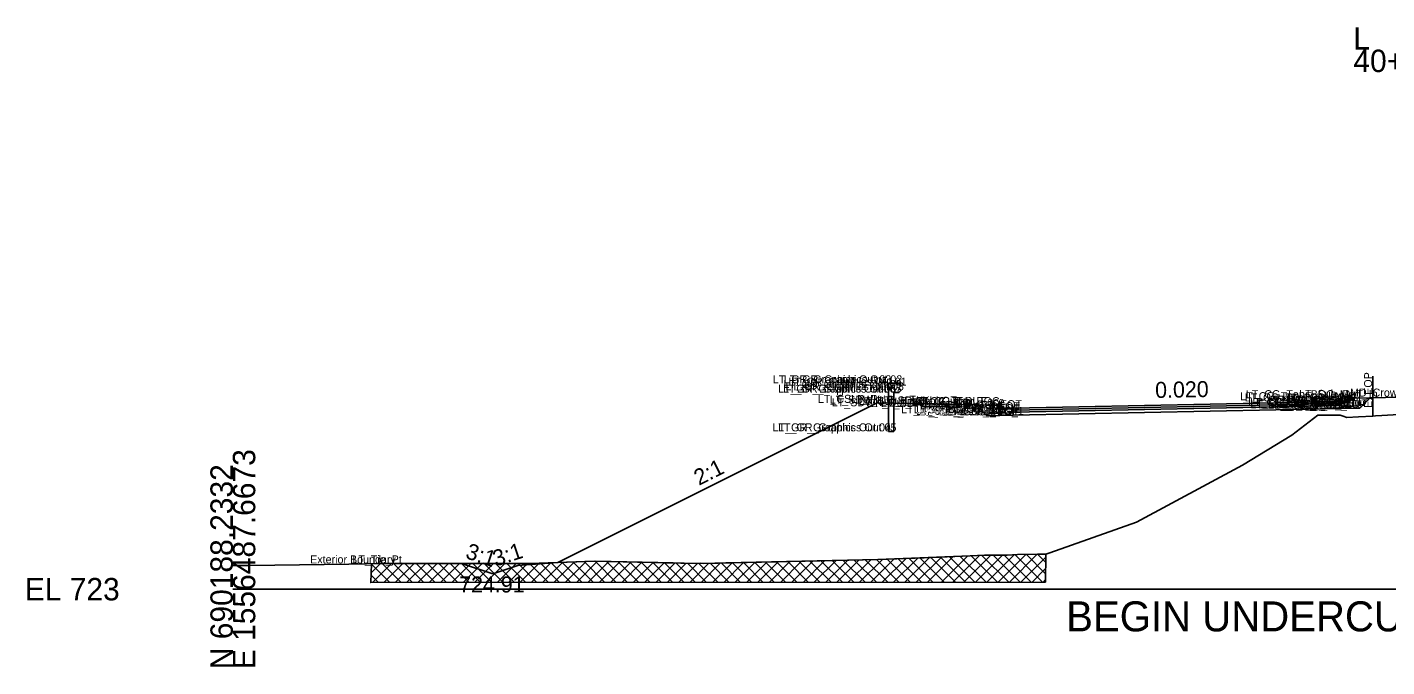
# Model space of a CAD drawing. Extents: x -26 to 6300, y -10 to 9577.
# Drawn here: x -25.7 to 144.2, y 6490.3 to 6570.2 of the extents above; entities that cross this region are included whole.
import ezdxf

# ---------------------------------------------------------------- set-up
doc = ezdxf.new("R2010")
doc.units = 0
for name, color, linetype in [('Default', 7, 'Continuous'), ('Exist Cross Section Cell', 7, 'Continuous'), ('Exist XS Ground Line', 7, 'Continuous'), ('Prop CMT Conc Surface', 7, 'Continuous'), ('Prop CMT Concrete Structures', 7, 'Continuous'), ('Prop CMT Guardrail Graphics', 7, 'Continuous'), ('Prop CMT Pvmt Course 1', 7, 'Continuous'), ('Prop CMT Pvmt Course 1 CG', 7, 'Continuous'), ('Prop CMT Pvmt Course 2', 7, 'Continuous'), ('Prop CMT Pvmt Course 3', 7, 'Continuous'), ('Prop CMT Pvmt Surface', 7, 'Continuous'), ('Prop CMT Slope Grass', 7, 'Continuous'), ('Prop CMT Subgrade Earthwork', 7, 'Continuous'), ('Prop XS DDE', 7, 'Continuous'), ('Prop XS DDE Text', 7, 'Continuous'), ('Prop XS Label Text', 7, 'Continuous'), ('Prop XS SE Text', 7, 'Continuous'), ('Prop XS Side Slope Text', 7, 'Continuous'), ('Prop XS Undercut Exc', 7, 'Continuous'), ('Prop XS Undercut Exc Hatch', 7, 'Continuous'), ('Prop XSC Text', 7, 'Continuous')]:
    doc.layers.add(name, color=color, linetype=linetype)

msp = doc.modelspace()

# ---------------------------------------------------------------- linework, layer by layer
at = {"layer": 'Exist Cross Section Cell'}
msp.add_line((0, 6500), (150, 6500), dxfattribs=at)
at = {"layer": 'Exist XS Ground Line'}
msp.add_lwpolyline([(0, 6502.94), (2.15, 6502.97), (14.48, 6503.13), (21.06, 6503.23), (37.12, 6503.19), (45.16, 6503.49), (57.75, 6503.22), (58.42, 6503.23), (58.81, 6503.22), (80.6, 6503.7), (92.13, 6504.15), (93.92, 6504.24), (96.73, 6504.24), (98.03, 6504.32), (100.53, 6504.36), (101.56, 6504.36), (102.06, 6504.54), (112.9, 6508.35), (126.16, 6515.5), (132.33, 6519.23), (135.58, 6521.72), (138.34, 6521.72), (138.74, 6521.59), (139.17, 6521.45), (140.65, 6521.54), (142.44, 6521.62), (142.77, 6521.66), (143.57, 6521.71), (149.23, 6522.02)], dxfattribs=at)
at = {"layer": 'Prop CMT Conc Surface'}
for points in [[(91, 6523.07), (86, 6523.17)], [(138.5, 6523.42), (139.25, 6523.44), (139.25, 6523.6), (140.01, 6523.85)], [(95.5, 6522.48), (95.5, 6522.98), (95, 6522.98)], [(97.5, 6522.6), (95.5, 6522.48)]]:
    msp.add_lwpolyline(points, dxfattribs=at)
at = {"layer": 'Prop CMT Concrete Structures'}
for points in [[(86, 6522.84), (86, 6523.17)], [(86, 6523.17), (91, 6523.07)], [(91, 6523.07), (91, 6522.74)], [(138.5, 6523.42), (139.25, 6523.44), (139.25, 6523.6), (140.01, 6523.85)], [(138.5, 6522.84), (138.5, 6523.42)], [(140.01, 6523.85), (140.01, 6522.87)], [(91, 6522.74), (86, 6522.84)], [(97.5, 6522.6), (95.5, 6522.48), (95.5, 6522.98), (95, 6522.98)], [(95, 6522.98), (95, 6521.97), (97.5, 6522.02)], [(97.5, 6522.02), (97.5, 6522.6)], [(140.01, 6522.87), (138.5, 6522.84)]]:
    msp.add_lwpolyline(points, dxfattribs=at)
at = {"layer": 'Prop CMT Guardrail Graphics'}
for points in [[(81.9, 6519.71), (81.9, 6525.71)], [(81.9, 6525.71), (83.23, 6525.71), (83.51, 6525.42)], [(83.51, 6524.84), (83.23, 6524.55), (82.57, 6524.55)], [(83.51, 6525.42), (83.23, 6525.13)], [(83.23, 6525.13), (83.51, 6524.84)], [(82.57, 6524.55), (82.57, 6519.71)], [(82.57, 6519.71), (81.9, 6519.71)]]:
    msp.add_lwpolyline(points, dxfattribs=at)
at = {"layer": 'Prop CMT Pvmt Course 1'}
for points in [[(138.5, 6523.42), (97.5, 6522.6)], [(97.5, 6522.35), (138.5, 6523.17)], [(138.5, 6523.17), (138.5, 6523.42)], [(138.5, 6523.17), (138.5, 6523.17), (138.5, 6523.17)], [(97.5, 6522.6), (97.5, 6522.35)]]:
    msp.add_lwpolyline(points, dxfattribs=at)
at = {"layer": 'Prop CMT Pvmt Course 1 CG'}
for points in [[(97.5, 6522.02), (94.5, 6521.96), (94.2, 6521.66)], [(94.2, 6521.66), (97.5, 6521.73)], [(97.5, 6521.77), (97.5, 6522.02)], [(138.5, 6522.84), (140.51, 6522.88), (140.8, 6522.59)], [(138.5, 6522.59), (138.5, 6522.84)], [(140.76, 6522.59), (138.5, 6522.55)]]:
    msp.add_lwpolyline(points, dxfattribs=at)
at = {"layer": 'Prop CMT Pvmt Course 2'}
for points in [[(138.5, 6523.17), (97.5, 6522.35)], [(138.5, 6522.92), (138.5, 6523.17)], [(97.5, 6522.1), (138.5, 6522.92)], [(97.5, 6522.35), (97.5, 6522.1)]]:
    msp.add_lwpolyline(points, dxfattribs=at)
at = {"layer": 'Prop CMT Pvmt Course 3'}
for points in [[(138.5, 6522.92), (97.5, 6522.1)], [(97.5, 6521.73), (138.5, 6522.55)], [(97.5, 6522.1), (97.5, 6521.73)], [(138.5, 6522.55), (138.5, 6522.92)]]:
    msp.add_lwpolyline(points, dxfattribs=at)
at = {"layer": 'Prop CMT Pvmt Surface'}
msp.add_lwpolyline([(138.5, 6523.42), (97.5, 6522.6)], dxfattribs=at)
at = {"layer": 'Prop CMT Slope Grass'}
msp.add_line((80.5, 6523.27), (40.59, 6503.32), dxfattribs=at)
for points in [[(95, 6522.98), (80.5, 6523.27)], [(140.01, 6523.85), (150, 6524.05)]]:
    msp.add_lwpolyline(points, dxfattribs=at)
at = {"layer": 'Prop CMT Subgrade Earthwork'}
msp.add_line((94.2, 6521.66), (92.84, 6523.02), dxfattribs=at)
for points in [[(142.1, 6523.89), (140.8, 6522.59)], [(97.5, 6521.73), (94.2, 6521.66)], [(138.5, 6522.55), (97.5, 6521.73)], [(140.8, 6522.59), (138.5, 6522.55)], [(138.5, 6522.55), (138.5, 6522.55)]]:
    msp.add_lwpolyline(points, dxfattribs=at)
at = {"layer": 'Prop XS DDE'}
for p, q in [((35.61, 6502.95), (32.48, 6501.91)), ((40.59, 6503.32), (35.61, 6502.95))]:
    msp.add_line(p, q, dxfattribs=at)
msp.add_lwpolyline([(32.48, 6501.91), (28.58, 6503.21)], dxfattribs=at)
at = {"layer": 'Prop XS Label Text'}
msp.add_line((142.44, 6526.62), (142.44, 6521.62), dxfattribs=at)
at = {"layer": 'Prop XS Undercut Exc'}
for p, q in [((100.53, 6504.36), (98.03, 6504.32)), ((101.56, 6504.36), (100.53, 6504.36)), ((101.55, 6500.89), (101.56, 6504.36)), ((25.95, 6500.83), (28.34, 6503.21)), ((84.11, 6503.83), (84.11, 6503.83)), ((86.36, 6503.92), (84.12, 6503.83)), ((92.13, 6504.15), (86.36, 6503.92)), ((93.92, 6504.24), (92.13, 6504.15)), ((95.32, 6504.24), (93.92, 6504.24)), ((96.73, 6504.24), (95.32, 6504.24)), ((98.03, 6504.32), (96.73, 6504.24)), ((101.27, 6500.89), (101.55, 6501.17))]:
    msp.add_line(p, q, dxfattribs=at)
for points in [[(25.03, 6503.22), (17.32, 6503.17), (17.23, 6500.82), (101.55, 6500.87)], [(40.59, 6503.32), (37.12, 6503.19), (25.03, 6503.22)], [(55.01, 6503.28), (45.34, 6503.49), (40.59, 6503.32)], [(84.12, 6503.83), (80.6, 6503.7), (61.6, 6503.28), (58.81, 6503.22), (58.42, 6503.23), (57.75, 6503.22), (55.01, 6503.28)]]:
    msp.add_lwpolyline(points, dxfattribs=at)
at = {"layer": 'Prop XS Undercut Exc Hatch'}
for p, q in [((95.6, 6500.88), (99.06, 6504.34)), ((97.02, 6500.88), (100.5, 6504.36)), ((99.14, 6504.34), (101.55, 6501.92)), ((100.53, 6504.36), (101.56, 6503.33)), ((17.28, 6502.05), (18.4, 6503.18)), ((17.32, 6503.13), (19.63, 6500.82)), ((17.46, 6500.82), (19.83, 6503.19)), ((18.69, 6503.18), (21.04, 6500.82)), ((18.88, 6500.82), (21.25, 6503.2)), ((20.09, 6503.19), (22.46, 6500.82)), ((20.29, 6500.82), (22.67, 6503.2)), ((21.5, 6503.2), (23.87, 6500.83)), ((21.71, 6500.82), (24.1, 6503.21)), ((22.9, 6503.21), (25.28, 6500.83)), ((23.12, 6500.82), (25.52, 6503.22)), ((24.31, 6503.21), (26.7, 6500.83)), ((24.54, 6500.83), (26.93, 6503.21)), ((25.72, 6503.22), (28.11, 6500.83)), ((27.14, 6503.21), (29.52, 6500.83)), ((27.37, 6500.83), (29.75, 6503.21)), ((28.56, 6503.21), (30.94, 6500.83)), ((28.78, 6500.83), (31.16, 6503.2)), ((29.97, 6503.21), (32.35, 6500.83)), ((30.2, 6500.83), (32.57, 6503.2)), ((31.39, 6503.2), (33.76, 6500.83)), ((31.61, 6500.83), (33.98, 6503.2)), ((32.81, 6503.2), (35.18, 6500.83)), ((33.03, 6500.83), (35.39, 6503.19)), ((34.23, 6503.19), (36.59, 6500.83)), ((34.44, 6500.83), (36.8, 6503.19)), ((35.65, 6503.19), (38, 6500.83)), ((35.86, 6500.83), (38.26, 6503.23)), ((37.06, 6503.19), (39.42, 6500.83)), ((37.27, 6500.83), (39.73, 6503.29)), ((38.43, 6503.24), (40.83, 6500.84)), ((38.69, 6500.83), (41.19, 6503.34)), ((39.79, 6503.29), (42.24, 6500.84)), ((40.1, 6500.84), (42.66, 6503.39)), ((41.16, 6503.34), (43.66, 6500.84)), ((41.52, 6500.84), (44.13, 6503.44)), ((42.52, 6503.39), (45.07, 6500.84)), ((42.93, 6500.84), (45.58, 6503.48)), ((43.89, 6503.44), (46.48, 6500.84)), ((44.35, 6500.84), (46.96, 6503.45)), ((45.25, 6503.48), (47.9, 6500.84)), ((45.76, 6500.84), (48.35, 6503.42)), ((46.69, 6503.46), (49.31, 6500.84)), ((47.18, 6500.84), (49.73, 6503.39)), ((48.14, 6503.43), (50.72, 6500.84)), ((48.59, 6500.84), (51.12, 6503.36)), ((49.58, 6503.4), (52.14, 6500.84)), ((50.01, 6500.84), (52.5, 6503.33)), ((51.03, 6503.36), (53.55, 6500.84)), ((51.42, 6500.84), (53.89, 6503.3)), ((52.47, 6503.33), (54.96, 6500.84)), ((52.84, 6500.84), (55.27, 6503.27)), ((53.92, 6503.3), (56.38, 6500.85)), ((54.25, 6500.84), (56.65, 6503.24)), ((55.36, 6503.27), (57.79, 6500.85)), ((55.67, 6500.84), (58.05, 6503.22)), ((56.81, 6503.24), (59.2, 6500.85)), ((57.08, 6500.85), (59.47, 6503.24)), ((58.24, 6503.22), (60.62, 6500.85)), ((58.5, 6500.85), (60.92, 6503.27)), ((59.64, 6503.24), (62.03, 6500.85)), ((59.91, 6500.85), (62.37, 6503.3)), ((61.02, 6503.27), (63.44, 6500.85)), ((61.33, 6500.85), (63.81, 6503.33)), ((62.41, 6503.3), (64.86, 6500.85)), ((62.74, 6500.85), (65.26, 6503.36)), ((63.79, 6503.33), (66.27, 6500.85)), ((64.16, 6500.85), (66.7, 6503.39)), ((65.18, 6503.36), (67.68, 6500.85)), ((65.57, 6500.85), (68.15, 6503.42)), ((66.56, 6503.39), (69.1, 6500.85)), ((66.99, 6500.85), (69.59, 6503.46)), ((67.94, 6503.42), (70.51, 6500.85)), ((68.41, 6500.85), (71.04, 6503.49)), ((69.33, 6503.45), (71.92, 6500.85)), ((69.82, 6500.85), (72.49, 6503.52)), ((70.71, 6503.48), (73.34, 6500.86)), ((71.24, 6500.85), (73.93, 6503.55)), ((72.1, 6503.51), (74.75, 6500.86)), ((72.65, 6500.86), (75.38, 6503.58)), ((73.48, 6503.54), (76.16, 6500.86)), ((74.07, 6500.86), (76.82, 6503.61)), ((74.86, 6503.57), (77.58, 6500.86)), ((75.48, 6500.86), (78.27, 6503.65)), ((76.25, 6503.6), (78.99, 6500.86)), ((76.9, 6500.86), (79.71, 6503.68)), ((77.63, 6503.63), (80.4, 6500.86)), ((78.31, 6500.86), (81.17, 6503.72)), ((79.02, 6503.66), (81.82, 6500.86)), ((79.73, 6500.86), (82.64, 6503.78)), ((80.4, 6503.69), (83.23, 6500.86)), ((81.14, 6500.86), (84.11, 6503.83)), ((81.76, 6503.74), (84.64, 6500.86)), ((82.56, 6500.86), (85.59, 6503.89)), ((83.12, 6503.8), (86.06, 6500.86)), ((83.97, 6500.86), (87.06, 6503.95)), ((84.49, 6503.85), (87.47, 6500.86)), ((85.39, 6500.86), (88.53, 6504.01)), ((85.85, 6503.9), (88.88, 6500.87)), ((86.8, 6500.86), (90, 6504.07)), ((87.21, 6503.96), (90.3, 6500.87)), ((88.41, 6504), (91.54, 6500.87)), ((88.52, 6500.86), (91.79, 6504.14)), ((89.53, 6504.05), (92.71, 6500.87)), ((89.94, 6500.87), (93.28, 6504.21)), ((90.89, 6504.1), (94.12, 6500.87)), ((91.35, 6500.87), (94.72, 6504.24)), ((92.25, 6504.15), (95.53, 6500.88)), ((92.77, 6500.87), (96.11, 6504.21)), ((93.59, 6504.22), (96.94, 6500.88)), ((94.19, 6500.87), (97.56, 6504.25)), ((94.99, 6504.24), (98.35, 6500.88)), ((96.43, 6504.22), (99.76, 6500.89)), ((97.8, 6504.26), (101.17, 6500.89)), ((98.44, 6500.88), (101.56, 6504)), ((17.27, 6501.77), (18.22, 6500.82)), ((99.86, 6500.89), (101.55, 6502.58))]:
    msp.add_line(p, q, dxfattribs=at)

# ---------------------------------------------------------------- texts
at = {"layer": 'Default'}
for s, height, p in [('LT_GR_Graphics Out 03', 1, (67.47, 6525.71)), ('LT_GR_Graphics Out 02', 1, (68.84, 6525.71)), ('LT_GR_Graphics Out 01', 1, (69.4, 6525.42)), ('LT_GR_Graphics Out 06', 1, (68.11, 6524.55)), ('LT_GR_Graphics Out 07', 1, (68.75, 6524.55)), ('LT_GR_Graphics Out 09', 1, (68.78, 6525.13)), ('LT_GR_Graphics Out 08', 1, (69.05, 6524.84)), ('LT_CG_Top_BOC_Med', 1, (126.57, 6523.85)), ('LT_Sub_DLT_In', 1, (133.22, 6523.89)), ('MD_Crown Point', 1, (139.58, 6524.05)), ('LT_CSLP_Pnt', 1, (73.1, 6523.27)), ('LT_SDWK_Out_Top', 1, (74.58, 6523.17)), ('LT_SDWK_Out_Bot', 1, (74.83, 6522.84)), ('LT_Sub_Trench_Out_DLT', 1, (78.22, 6523.02)), ('LT_SDWK_In_Top', 1, (80.74, 6523.07)), ('LT_SDWK_In_Bot', 1, (80.99, 6522.74)), ('LT_CG_Top_BOC', 1, (84.81, 6522.98)), ('LT_CG_Top_Face', 1, (85.34, 6522.98)), ('LT_CG_Top_Gut', 1, (85.87, 6522.48)), ('LT_PV2_OEOT', 1, (88.99, 6522.35)), ('LT_PV3_OEOT', 1, (88.99, 6522.1)), ('LT_PV1_OEOT', 1, (89.23, 6522.6)), ('LT_CG_Bot_IE', 1, (89.34, 6522.02)), ('LT_CG_Top_Face_Med', 1, (125.87, 6523.6)), ('LT_CG_Top_Gut_Med', 1, (126.42, 6523.44)), ('LT_CG_Bot_BOC_Med', 1, (126.85, 6522.87)), ('LT_CG_Bot_IE_Med', 1, (127.09, 6522.84)), ('LT_Sub_IEOT_CG_1', 1, (127.13, 6522.59)), ('LT_PV2_OEEOP', 1, (129.29, 6523.17)), ('LT_PV3_OEEOP', 1, (129.29, 6522.92)), ('LT_Sub_OEEOP', 1, (129.33, 6522.55)), ('LT_PV2_IEEOP', 1, (130.05, 6523.17)), ('LT_Sub_IEEOP', 1, (130.09, 6522.55)), ('LT_CG1_Shelf_In', 1, (130.71, 6522.88)), ('LT_PV2_PGL', 1, (131.26, 6523.17)), ('LT_Sub_PGL', 1, (131.31, 6522.55)), ('LT_PV1_PGL', 1, (131.5, 6523.42)), ('LT_Sub_IEOP', 1, (133.05, 6522.63)), ('LT_CG1_Shelf_Out', 1, (83.48, 6521.96)), ('LT_CG_Bot_BOC', 1, (85.09, 6521.97)), ('LT_Sub_OEOT_CG_1', 1, (85.36, 6521.77)), ('LT_Sub_OEOP', 1, (85.77, 6521.7)), ('LT_Sub_OEOT', 1, (89.04, 6521.73)), ('LT_GR_Graphics Out 04', 1, (67.44, 6519.71)), ('LT_GR_Graphics Out 05', 1, (68.12, 6519.71)), ('Exterior Boundary', 1, (9.66, 6503.22)), ('LT_Tie_Pt', 1, (14.94, 6503.22)), ('-', 0.0001, (0, 6500))]:
    msp.add_text(s, height=height, dxfattribs=at).set_placement(p)
at = {"layer": 'Exist Cross Section Cell'}
for s, p in [('L', (140, 6567.38)), ('40+00.00 / 1', (140, 6564.58)), ('EL 723', (-26, 6498.6))]:
    msp.add_text(s, height=2.8, dxfattribs=at).set_placement(p)
for s, p in [('E 1556487.6673', (2.8, 6490)), ('N 690188.2332', (0, 6490))]:
    msp.add_text(s, height=2.8, rotation=90, dxfattribs=at).set_placement(p)
at = {"layer": 'Prop XS DDE Text'}
for rotation, p in [(341.5651, (28.95, 6503.91)), (17.9773, (32.87, 6502.82))]:
    msp.add_text('3:1', height=2, rotation=rotation, dxfattribs=at).set_placement(p)
msp.add_text('724.91', height=2, dxfattribs=at).set_placement((28.27, 6499.59))
at = {"layer": 'Prop XS Label Text'}
msp.add_text('E. EOP', height=1, rotation=90, dxfattribs=at).set_placement((142.34, 6522.64))
at = {"layer": 'Prop XS SE Text'}
msp.add_text('0.020', height=2, rotation=1.1458, dxfattribs=at).set_placement((115.25, 6523.87))
at = {"layer": 'Prop XS Side Slope Text'}
msp.add_text('2:1', height=2, rotation=26.5651, dxfattribs=at).set_placement((58.24, 6512.9))
at = {"layer": 'Prop XSC Text'}
msp.add_text('BEGIN UNDERCUT AT STA 39+75', height=3.75, dxfattribs=at).set_placement((104.12, 6494.73))

doc.saveas('drawing.dxf')
